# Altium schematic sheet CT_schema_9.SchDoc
size 147 x 119 mm
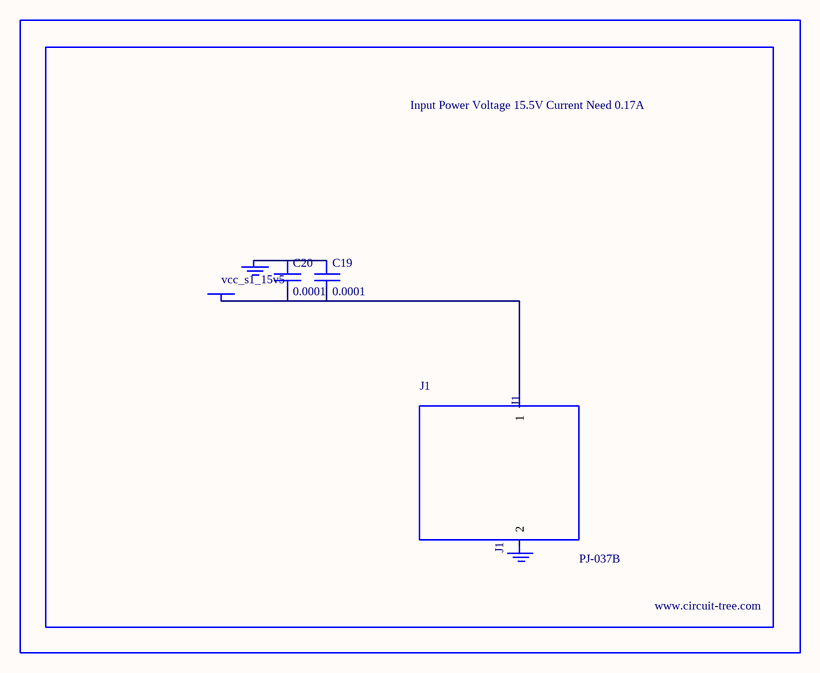
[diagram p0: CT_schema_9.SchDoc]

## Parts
BORDER8  (no value)
C19  0.0001  [EXV-9H]
C20  0.0001  [EXV-9H]
GND_INSTANCE_8_0  (no value)
GND_INSTANCE_8_1  (no value)
J1  PJ-037B  [PJ-037B_PACKAGE]
POWER_INSTANCE_8_0  vcc_s1_15v5

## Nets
NetC19_1: C19.1 C20.1 GND_INSTANCE_8_0.0(GND)
NetC19_2: C19.2 C20.2 J1.1 POWER_INSTANCE_8_0.0(PWR)

Not connected (* = marked no-connect by the designer): GND_INSTANCE_8_1 0(GND); J1 2

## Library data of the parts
BORDER8 = BORDER_PAGE8
C19 C20 = EDK107M035A9HAA
GND_INSTANCE_8_0 GND_INSTANCE_8_1 = GND
POWER_INSTANCE_8_0 = PWR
